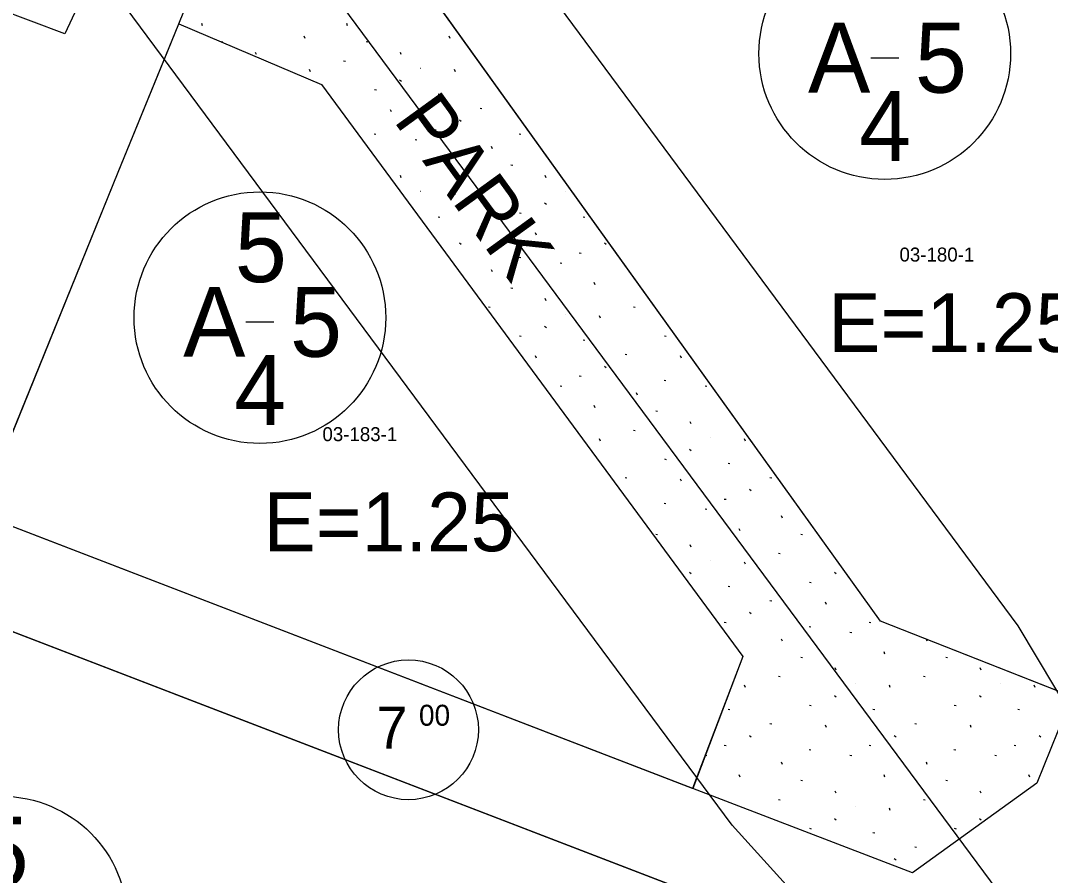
# Model space of a CAD drawing. Extents: x 413946 to 415528, y 4453939 to 4454944.
# Drawn here: x 414534.5 to 414608.2, y 4454129.1 to 4454190.2 of the extents above; entities that cross this region are included whole.
import ezdxf

# ---------------------------------------------------------------- set-up
doc = ezdxf.new("R2010")
doc.units = 0
for name, color, linetype in [('0_KADASTRO', 7, 'Continuous'), ('HAT_ENERJI_NAKIL_HAT', 7, 'Continuous'), ('KST_ENERJI_NAKIL_HAT', 7, 'Continuous'), ('Level 28', 7, 'Continuous'), ('Level 33', 7, 'Continuous'), ('Level 41', 7, 'Continuous'), ('Level 54', 7, 'Continuous'), ('SEMBOL', 7, 'Continuous'), ('SNR_FONKSIYON', 7, 'Continuous')]:
    doc.layers.add(name, color=color, linetype=linetype)

msp = doc.modelspace()

# ---------------------------------------------------------------- linework, layer by layer
at = {"layer": '0_KADASTRO'}
for points in [[(414559.099, 4454198.729), (414562.117, 4454206.023), (414565.063, 4454213.144), (414629.667, 4454191.292), (414609.707, 4454141.877), (414608.612, 4454142.309), (414596.035, 4454147.274)], [(414531.54, 4454154.946), (414541.502, 4454179.388), (414544.778, 4454187.433), (414545.825, 4454189.992), (414556.039, 4454185.652), (414586.169, 4454144.76), (414582.845, 4454135.996), (414582.587, 4454135.319)], [(414506.487, 4454115.516), (414521.332, 4454151.366), (414594.268, 4454123.334), (414578.644, 4454085.643)]]:
    msp.add_lwpolyline(points, close=True, dxfattribs=at)
at = {"layer": 'HAT_ENERJI_NAKIL_HAT'}
msp.add_lwpolyline([(414658.516, 4453939.478), (414647.224, 4454070.234), (413999.883, 4454943.957)], dxfattribs=at)
at = {"layer": 'KST_ENERJI_NAKIL_HAT'}
for p, q in [((414502.822, 4454286.061), (414605.839, 4454146.942)), ((414585.402, 4454132.688), (414483.626, 4454269.972)), ((414605.839, 4454146.942), (414649.751, 4454073.6)), ((414643.325, 4454068.836), (414585.402, 4454132.688))]:
    msp.add_line(p, q, dxfattribs=at)
at = {"layer": 'Level 28'}
for p, q in [((414550.888, 4454217.901), (414537.675, 4454189.275)), ((414545.821, 4454189.994), (414556.436, 4454216.062)), ((414537.675, 4454189.275), (414488.322, 4454207.851)), ((414541.502, 4454179.388), (414545.821, 4454189.994)), ((414531.54, 4454154.946), (414541.502, 4454179.388)), ((414582.588, 4454135.319), (414531.54, 4454154.946)), ((414521.332, 4454151.366), (414594.268, 4454123.334)), ((414609.707, 4454141.877), (414607.21, 4454135.694)), ((414607.21, 4454135.694), (414598.316, 4454129.272)), ((414598.316, 4454129.272), (414582.588, 4454135.319))]:
    msp.add_line(p, q, dxfattribs=at)
at = {"layer": 'Level 41'}
for p, q in [((414535.579, 4454190.064), (414535.555, 4454190.123)), ((414535.579, 4454190.064), (414535.555, 4454190.123)), ((414547.535, 4454189.866), (414547.469, 4454190.028)), ((414547.535, 4454189.866), (414547.469, 4454190.028)), ((414557.903, 4454189.866), (414557.837, 4454190.028)), ((414557.903, 4454189.866), (414557.837, 4454190.028)), ((414548.854, 4454188.731), (414548.98, 4454188.707)), ((414548.854, 4454188.731), (414548.98, 4454188.707)), ((414554.872, 4454188.951), (414554.807, 4454189.115)), ((414554.872, 4454188.951), (414554.807, 4454189.115)), ((414559.222, 4454188.731), (414559.348, 4454188.707)), ((414559.222, 4454188.731), (414559.348, 4454188.707)), ((414565.24, 4454188.951), (414565.175, 4454189.115)), ((414565.24, 4454188.951), (414565.175, 4454189.115)), ((414551.376, 4454187.802), (414551.312, 4454187.963)), ((414551.376, 4454187.802), (414551.312, 4454187.963)), ((414561.744, 4454187.802), (414561.68, 4454187.963)), ((414561.744, 4454187.802), (414561.68, 4454187.963)), ((414557.618, 4454187.363), (414557.745, 4454187.339)), ((414557.618, 4454187.363), (414557.745, 4454187.339)), ((414555.254, 4454186.569), (414555.189, 4454186.731)), ((414555.254, 4454186.569), (414555.189, 4454186.731)), ((414563.102, 4454186.838), (414563.111, 4454186.837)), ((414563.102, 4454186.838), (414563.111, 4454186.837)), ((414565.622, 4454186.569), (414565.557, 4454186.731)), ((414565.622, 4454186.569), (414565.557, 4454186.731)), ((414561.627, 4454186), (414561.754, 4454185.901)), ((414561.627, 4454186), (414561.754, 4454185.901)), ((414559.833, 4454185.295), (414559.96, 4454185.27)), ((414559.833, 4454185.295), (414559.96, 4454185.27)), ((414564.381, 4454185.001), (414564.508, 4454184.977)), ((414564.381, 4454185.001), (414564.508, 4454184.977)), ((414561.047, 4454183.697), (414560.982, 4454183.859)), ((414561.047, 4454183.697), (414560.982, 4454183.859)), ((414567.381, 4454183.977), (414567.506, 4454183.952)), ((414567.381, 4454183.977), (414567.506, 4454183.952)), ((414565.906, 4454183.139), (414566.033, 4454183.039)), ((414565.906, 4454183.139), (414566.033, 4454183.039)), ((414559.806, 4454182.129), (414559.933, 4454182.106)), ((414559.806, 4454182.129), (414559.933, 4454182.106)), ((414564.111, 4454182.433), (414564.238, 4454182.41)), ((414564.111, 4454182.433), (414564.238, 4454182.41)), ((414570.174, 4454182.129), (414570.301, 4454182.106)), ((414570.174, 4454182.129), (414570.301, 4454182.106)), ((414562.736, 4454181.719), (414562.862, 4454181.695)), ((414562.736, 4454181.719), (414562.862, 4454181.695)), ((414568.271, 4454181.06), (414568.205, 4454181.222)), ((414568.271, 4454181.06), (414568.205, 4454181.222)), ((414565.24, 4454180.145), (414565.175, 4454180.309)), ((414565.24, 4454180.145), (414565.175, 4454180.309)), ((414569.59, 4454179.925), (414569.716, 4454179.901)), ((414569.59, 4454179.925), (414569.716, 4454179.901)), ((414561.744, 4454178.996), (414561.68, 4454179.157)), ((414561.744, 4454178.996), (414561.68, 4454179.157)), ((414572.112, 4454178.996), (414572.048, 4454179.157)), ((414572.112, 4454178.996), (414572.048, 4454179.157)), ((414567.986, 4454178.557), (414568.113, 4454178.533)), ((414567.986, 4454178.557), (414568.113, 4454178.533)), ((414563.102, 4454178.032), (414563.111, 4454178.031)), ((414563.102, 4454178.032), (414563.111, 4454178.031)), ((414565.622, 4454177.763), (414565.557, 4454177.925)), ((414565.622, 4454177.763), (414565.557, 4454177.925)), ((414573.47, 4454178.032), (414573.479, 4454178.031)), ((414573.47, 4454178.032), (414573.479, 4454178.031)), ((414571.995, 4454177.194), (414572.122, 4454177.095)), ((414571.995, 4454177.194), (414572.122, 4454177.095)), ((414564.381, 4454176.195), (414564.508, 4454176.171)), ((414564.381, 4454176.195), (414564.508, 4454176.171)), ((414570.201, 4454176.489), (414570.328, 4454176.464)), ((414570.201, 4454176.489), (414570.328, 4454176.464)), ((414574.749, 4454176.195), (414574.876, 4454176.171)), ((414574.749, 4454176.195), (414574.876, 4454176.171)), ((414567.381, 4454175.171), (414567.506, 4454175.146)), ((414567.381, 4454175.171), (414567.506, 4454175.146)), ((414571.415, 4454174.891), (414571.35, 4454175.053)), ((414571.415, 4454174.891), (414571.35, 4454175.053)), ((414565.906, 4454174.333), (414566.033, 4454174.233)), ((414565.906, 4454174.333), (414566.033, 4454174.233)), ((414576.274, 4454174.333), (414576.401, 4454174.233)), ((414576.274, 4454174.333), (414576.401, 4454174.233)), ((414570.174, 4454173.323), (414570.301, 4454173.3)), ((414570.174, 4454173.323), (414570.301, 4454173.3)), ((414574.479, 4454173.627), (414574.606, 4454173.604)), ((414574.479, 4454173.627), (414574.606, 4454173.604)), ((414573.104, 4454172.913), (414573.23, 4454172.889)), ((414573.104, 4454172.913), (414573.23, 4454172.889)), ((414568.271, 4454172.254), (414568.205, 4454172.416)), ((414568.271, 4454172.254), (414568.205, 4454172.416)), ((414569.59, 4454171.119), (414569.716, 4454171.095)), ((414569.59, 4454171.119), (414569.716, 4454171.095)), ((414575.608, 4454171.339), (414575.543, 4454171.503)), ((414575.608, 4454171.339), (414575.543, 4454171.503)), ((414572.112, 4454170.19), (414572.048, 4454170.351)), ((414572.112, 4454170.19), (414572.048, 4454170.351)), ((414567.986, 4454169.751), (414568.113, 4454169.727)), ((414567.986, 4454169.751), (414568.113, 4454169.727)), ((414578.354, 4454169.751), (414578.481, 4454169.727)), ((414578.354, 4454169.751), (414578.481, 4454169.727)), ((414573.47, 4454169.226), (414573.479, 4454169.225)), ((414573.47, 4454169.226), (414573.479, 4454169.225)), ((414575.99, 4454168.957), (414575.925, 4454169.119)), ((414575.99, 4454168.957), (414575.925, 4454169.119)), ((414571.995, 4454168.388), (414572.122, 4454168.289)), ((414571.995, 4454168.388), (414572.122, 4454168.289)), ((414570.201, 4454167.683), (414570.328, 4454167.658)), ((414570.201, 4454167.683), (414570.328, 4454167.658)), ((414574.749, 4454167.389), (414574.876, 4454167.365)), ((414574.749, 4454167.389), (414574.876, 4454167.365)), ((414580.569, 4454167.683), (414580.696, 4454167.658)), ((414580.569, 4454167.683), (414580.696, 4454167.658)), ((414571.415, 4454166.085), (414571.35, 4454166.247)), ((414571.415, 4454166.085), (414571.35, 4454166.247)), ((414577.749, 4454166.365), (414577.874, 4454166.34)), ((414577.749, 4454166.365), (414577.874, 4454166.34)), ((414581.783, 4454166.085), (414581.718, 4454166.247)), ((414581.783, 4454166.085), (414581.718, 4454166.247)), ((414576.274, 4454165.527), (414576.401, 4454165.427)), ((414576.274, 4454165.527), (414576.401, 4454165.427)), ((414574.479, 4454164.821), (414574.606, 4454164.798)), ((414574.479, 4454164.821), (414574.606, 4454164.798)), ((414580.542, 4454164.517), (414580.669, 4454164.494)), ((414580.542, 4454164.517), (414580.669, 4454164.494)), ((414573.104, 4454164.107), (414573.23, 4454164.083)), ((414573.104, 4454164.107), (414573.23, 4454164.083)), ((414578.639, 4454163.448), (414578.573, 4454163.61)), ((414578.639, 4454163.448), (414578.573, 4454163.61)), ((414583.472, 4454164.107), (414583.598, 4454164.083)), ((414583.472, 4454164.107), (414583.598, 4454164.083)), ((414575.608, 4454162.533), (414575.543, 4454162.697)), ((414575.608, 4454162.533), (414575.543, 4454162.697)), ((414579.958, 4454162.313), (414580.084, 4454162.289)), ((414579.958, 4454162.313), (414580.084, 4454162.289)), ((414582.48, 4454161.384), (414582.416, 4454161.545)), ((414582.48, 4454161.384), (414582.416, 4454161.545)), ((414578.354, 4454160.945), (414578.481, 4454160.921)), ((414578.354, 4454160.945), (414578.481, 4454160.921)), ((414575.99, 4454160.151), (414575.925, 4454160.313)), ((414575.99, 4454160.151), (414575.925, 4454160.313)), ((414583.838, 4454160.42), (414583.847, 4454160.419)), ((414583.838, 4454160.42), (414583.847, 4454160.419)), ((414586.358, 4454160.151), (414586.293, 4454160.313)), ((414586.358, 4454160.151), (414586.293, 4454160.313)), ((414582.363, 4454159.582), (414582.49, 4454159.483)), ((414582.363, 4454159.582), (414582.49, 4454159.483)), ((414580.569, 4454158.877), (414580.696, 4454158.852)), ((414580.569, 4454158.877), (414580.696, 4454158.852)), ((414585.117, 4454158.583), (414585.244, 4454158.559)), ((414585.117, 4454158.583), (414585.244, 4454158.559)), ((414577.749, 4454157.559), (414577.874, 4454157.534)), ((414577.749, 4454157.559), (414577.874, 4454157.534)), ((414581.783, 4454157.279), (414581.718, 4454157.441)), ((414581.783, 4454157.279), (414581.718, 4454157.441)), ((414588.117, 4454157.559), (414588.242, 4454157.534)), ((414588.117, 4454157.559), (414588.242, 4454157.534)), ((414586.642, 4454156.721), (414586.769, 4454156.621)), ((414586.642, 4454156.721), (414586.769, 4454156.621)), ((414580.542, 4454155.711), (414580.669, 4454155.688)), ((414580.542, 4454155.711), (414580.669, 4454155.688)), ((414584.847, 4454156.015), (414584.974, 4454155.992)), ((414584.847, 4454156.015), (414584.974, 4454155.992)), ((414583.472, 4454155.301), (414583.598, 4454155.277)), ((414583.472, 4454155.301), (414583.598, 4454155.277)), ((414589.007, 4454154.642), (414588.941, 4454154.804)), ((414589.007, 4454154.642), (414588.941, 4454154.804)), ((414579.958, 4454153.507), (414580.084, 4454153.483)), ((414579.958, 4454153.507), (414580.084, 4454153.483)), ((414585.976, 4454153.727), (414585.911, 4454153.891)), ((414585.976, 4454153.727), (414585.911, 4454153.891)), ((414590.326, 4454153.507), (414590.452, 4454153.483)), ((414590.326, 4454153.507), (414590.452, 4454153.483)), ((414582.48, 4454152.578), (414582.416, 4454152.739)), ((414582.48, 4454152.578), (414582.416, 4454152.739)), ((414588.722, 4454152.139), (414588.849, 4454152.115)), ((414588.722, 4454152.139), (414588.849, 4454152.115)), ((414583.838, 4454151.614), (414583.847, 4454151.613)), ((414583.838, 4454151.614), (414583.847, 4454151.613)), ((414586.358, 4454151.345), (414586.293, 4454151.507)), ((414586.358, 4454151.345), (414586.293, 4454151.507)), ((414582.363, 4454150.776), (414582.49, 4454150.677)), ((414582.363, 4454150.776), (414582.49, 4454150.677)), ((414592.731, 4454150.776), (414592.858, 4454150.677)), ((414592.731, 4454150.776), (414592.858, 4454150.677)), ((414585.117, 4454149.777), (414585.244, 4454149.753)), ((414585.117, 4454149.777), (414585.244, 4454149.753)), ((414590.937, 4454150.071), (414591.064, 4454150.046)), ((414590.937, 4454150.071), (414591.064, 4454150.046)), ((414588.117, 4454148.753), (414588.242, 4454148.728)), ((414588.117, 4454148.753), (414588.242, 4454148.728)), ((414592.151, 4454148.473), (414592.086, 4454148.635)), ((414592.151, 4454148.473), (414592.086, 4454148.635)), ((414586.642, 4454147.915), (414586.769, 4454147.815)), ((414586.642, 4454147.915), (414586.769, 4454147.815)), ((414584.847, 4454147.209), (414584.974, 4454147.186)), ((414584.847, 4454147.209), (414584.974, 4454147.186)), ((414590.91, 4454146.905), (414591.037, 4454146.882)), ((414590.91, 4454146.905), (414591.037, 4454146.882)), ((414595.215, 4454147.209), (414595.342, 4454147.186)), ((414595.215, 4454147.209), (414595.342, 4454147.186)), ((414589.007, 4454145.836), (414588.941, 4454145.998)), ((414589.007, 4454145.836), (414588.941, 4454145.998)), ((414593.84, 4454146.495), (414593.966, 4454146.471)), ((414593.84, 4454146.495), (414593.966, 4454146.471)), ((414599.375, 4454145.836), (414599.317, 4454145.978)), ((414599.375, 4454145.836), (414599.317, 4454145.978)), ((414590.326, 4454144.701), (414590.452, 4454144.677)), ((414590.326, 4454144.701), (414590.452, 4454144.677)), ((414596.344, 4454144.921), (414596.279, 4454145.085)), ((414596.344, 4454144.921), (414596.279, 4454145.085)), ((414600.694, 4454144.701), (414600.82, 4454144.677)), ((414600.694, 4454144.701), (414600.82, 4454144.677)), ((414592.848, 4454143.772), (414592.784, 4454143.933)), ((414592.848, 4454143.772), (414592.784, 4454143.933)), ((414603.216, 4454143.772), (414603.152, 4454143.933)), ((414603.216, 4454143.772), (414603.152, 4454143.933)), ((414588.722, 4454143.333), (414588.849, 4454143.309)), ((414588.722, 4454143.333), (414588.849, 4454143.309)), ((414599.09, 4454143.333), (414599.217, 4454143.309)), ((414599.09, 4454143.333), (414599.217, 4454143.309)), ((414586.358, 4454142.539), (414586.293, 4454142.701)), ((414586.358, 4454142.539), (414586.293, 4454142.701)), ((414594.206, 4454142.808), (414594.215, 4454142.807)), ((414594.206, 4454142.808), (414594.215, 4454142.807)), ((414596.726, 4454142.539), (414596.661, 4454142.701)), ((414596.726, 4454142.539), (414596.661, 4454142.701)), ((414604.574, 4454142.808), (414604.583, 4454142.807)), ((414604.574, 4454142.808), (414604.583, 4454142.807)), ((414607.094, 4454142.539), (414607.029, 4454142.701)), ((414607.094, 4454142.539), (414607.029, 4454142.701)), ((414592.731, 4454141.97), (414592.858, 4454141.871)), ((414592.731, 4454141.97), (414592.858, 4454141.871)), ((414603.099, 4454141.97), (414603.226, 4454141.871)), ((414603.099, 4454141.97), (414603.226, 4454141.871)), ((414585.117, 4454140.971), (414585.244, 4454140.947)), ((414585.117, 4454140.971), (414585.244, 4454140.947)), ((414590.937, 4454141.265), (414591.064, 4454141.24)), ((414590.937, 4454141.265), (414591.064, 4454141.24)), ((414595.485, 4454140.971), (414595.612, 4454140.947)), ((414595.485, 4454140.971), (414595.612, 4454140.947)), ((414601.305, 4454141.265), (414601.432, 4454141.24)), ((414601.305, 4454141.265), (414601.432, 4454141.24)), ((414605.853, 4454140.971), (414605.98, 4454140.947)), ((414605.853, 4454140.971), (414605.98, 4454140.947)), ((414588.117, 4454139.947), (414588.242, 4454139.922)), ((414588.117, 4454139.947), (414588.242, 4454139.922)), ((414592.151, 4454139.667), (414592.086, 4454139.829)), ((414592.151, 4454139.667), (414592.086, 4454139.829)), ((414598.485, 4454139.947), (414598.61, 4454139.922)), ((414598.485, 4454139.947), (414598.61, 4454139.922)), ((414602.519, 4454139.667), (414602.454, 4454139.829)), ((414602.519, 4454139.667), (414602.454, 4454139.829)), ((414586.642, 4454139.109), (414586.769, 4454139.009)), ((414586.642, 4454139.109), (414586.769, 4454139.009)), ((414597.01, 4454139.109), (414597.137, 4454139.009)), ((414597.01, 4454139.109), (414597.137, 4454139.009)), ((414607.378, 4454139.109), (414607.505, 4454139.009)), ((414607.378, 4454139.109), (414607.505, 4454139.009)), ((414584.847, 4454138.403), (414584.974, 4454138.38)), ((414584.847, 4454138.403), (414584.974, 4454138.38)), ((414590.91, 4454138.099), (414591.037, 4454138.076)), ((414590.91, 4454138.099), (414591.037, 4454138.076)), ((414595.215, 4454138.403), (414595.342, 4454138.38)), ((414595.215, 4454138.403), (414595.342, 4454138.38)), ((414601.278, 4454138.099), (414601.405, 4454138.076)), ((414601.278, 4454138.099), (414601.405, 4454138.076)), ((414605.583, 4454138.403), (414605.71, 4454138.38)), ((414605.583, 4454138.403), (414605.71, 4454138.38)), ((414583.486, 4454137.686), (414583.598, 4454137.665)), ((414583.486, 4454137.686), (414583.598, 4454137.665)), ((414589.007, 4454137.03), (414588.941, 4454137.192)), ((414589.007, 4454137.03), (414588.941, 4454137.192)), ((414593.84, 4454137.689), (414593.966, 4454137.665)), ((414593.84, 4454137.689), (414593.966, 4454137.665)), ((414599.375, 4454137.03), (414599.309, 4454137.192)), ((414599.375, 4454137.03), (414599.309, 4454137.192)), ((414604.208, 4454137.689), (414604.334, 4454137.665)), ((414604.208, 4454137.689), (414604.334, 4454137.665)), ((414585.976, 4454136.115), (414585.911, 4454136.279)), ((414585.976, 4454136.115), (414585.911, 4454136.279)), ((414590.326, 4454135.895), (414590.452, 4454135.871)), ((414590.326, 4454135.895), (414590.452, 4454135.871)), ((414596.344, 4454136.115), (414596.279, 4454136.279)), ((414596.344, 4454136.115), (414596.279, 4454136.279)), ((414600.694, 4454135.895), (414600.82, 4454135.871)), ((414600.694, 4454135.895), (414600.82, 4454135.871)), ((414606.712, 4454136.115), (414606.647, 4454136.279)), ((414606.712, 4454136.115), (414606.647, 4454136.279)), ((414592.848, 4454134.966), (414592.784, 4454135.127)), ((414592.848, 4454134.966), (414592.784, 4454135.127)), ((414603.216, 4454134.966), (414603.152, 4454135.127)), ((414603.216, 4454134.966), (414603.152, 4454135.127)), ((414588.722, 4454134.527), (414588.849, 4454134.503)), ((414588.722, 4454134.527), (414588.849, 4454134.503)), ((414599.09, 4454134.527), (414599.217, 4454134.503)), ((414599.09, 4454134.527), (414599.217, 4454134.503)), ((414586.293, 4454133.895), (414586.293, 4454133.895)), ((414586.293, 4454133.895), (414586.293, 4454133.895)), ((414594.206, 4454134.002), (414594.215, 4454134.001)), ((414594.206, 4454134.002), (414594.215, 4454134.001)), ((414596.726, 4454133.733), (414596.661, 4454133.895)), ((414596.726, 4454133.733), (414596.661, 4454133.895)), ((414604.574, 4454134.002), (414604.583, 4454134.001)), ((414604.574, 4454134.002), (414604.583, 4454134.001)), ((414592.731, 4454133.164), (414592.858, 4454133.065)), ((414592.731, 4454133.164), (414592.858, 4454133.065)), ((414603.099, 4454133.164), (414603.226, 4454133.065)), ((414603.099, 4454133.164), (414603.226, 4454133.065)), ((414590.937, 4454132.459), (414591.064, 4454132.434)), ((414590.937, 4454132.459), (414591.064, 4454132.434)), ((414595.485, 4454132.165), (414595.612, 4454132.141)), ((414595.485, 4454132.165), (414595.612, 4454132.141)), ((414601.305, 4454132.459), (414601.432, 4454132.434)), ((414601.305, 4454132.459), (414601.432, 4454132.434)), ((414598.485, 4454131.141), (414598.61, 4454131.116)), ((414598.485, 4454131.141), (414598.61, 4454131.116)), ((414597.01, 4454130.303), (414597.137, 4454130.203)), ((414597.01, 4454130.303), (414597.137, 4454130.203))]:
    msp.add_line(p, q, dxfattribs=at)
at = {"layer": 'Level 54'}
for points in [[(414629.667, 4454191.292), (414609.707, 4454141.877), (414596.035, 4454147.274), (414559.099, 4454198.729), (414562.117, 4454206.023), (414565.063, 4454213.144)], [(414556.039, 4454185.652), (414586.169, 4454144.76), (414582.588, 4454135.319), (414531.54, 4454154.946), (414541.502, 4454179.388), (414545.821, 4454189.994)], [(414578.644, 4454085.643), (414506.487, 4454115.516), (414521.332, 4454151.366), (414594.268, 4454123.334)]]:
    msp.add_lwpolyline(points, close=True, dxfattribs=at)
at = {"layer": 'SEMBOL'}
for p, q in [((414595.331, 4454187.576), (414597.331, 4454187.576)), ((414550.63, 4454168.688), (414552.63, 4454168.688))]:
    msp.add_line(p, q, dxfattribs=at)
for centre, radius in [((414596.331, 4454187.872), 9), ((414551.63, 4454168.985), 9), ((414562.258, 4454139.507), 5), ((414533.162, 4454125.753), 9)]:
    msp.add_circle(centre, radius, dxfattribs=at)
at = {"layer": 'SNR_FONKSIYON'}
for p, q in [((414596.035, 4454147.274), (414559.099, 4454198.729)), ((414545.821, 4454189.994), (414556.039, 4454185.652)), ((414556.039, 4454185.652), (414586.169, 4454144.76)), ((414609.707, 4454141.877), (414596.035, 4454147.274)), ((414586.169, 4454144.76), (414582.588, 4454135.319))]:
    msp.add_line(p, q, dxfattribs=at)

# ---------------------------------------------------------------- texts
at = {"layer": '0_KADASTRO'}
for s, p in [('03-180-1', (414597.382, 4454172.999)), ('03-183-1', (414556.103, 4454160.153))]:
    msp.add_text(s, height=1, dxfattribs=at).set_placement(p)
at = {"layer": 'Level 33'}
msp.add_text('PARK', height=4, rotation=305.8953, dxfattribs=at).set_placement((414561.12, 4454183.113))
at = {"layer": 'SEMBOL'}
for s, height, p in [('A', 5, (414590.839, 4454185.076)), ('5', 5, (414598.485, 4454185.076)), ('4', 5, (414594.493, 4454180.199)), ('5', 5, (414549.838, 4454171.527)), ('A', 5, (414546.138, 4454166.188)), ('5', 5, (414553.784, 4454166.188)), ('E=1.25', 4.2, (414592.281, 4454166.533)), ('4', 5, (414549.792, 4454161.311)), ('E=1.25', 4.2, (414551.886, 4454152.28)), ('7', 3, (414559.962, 4454138.167)), ('00', 1.5, (414563.008, 4454139.798)), ('5', 5, (414531.37, 4454128.295))]:
    msp.add_text(s, height=height, dxfattribs=at).set_placement(p)

doc.saveas('drawing.dxf')
